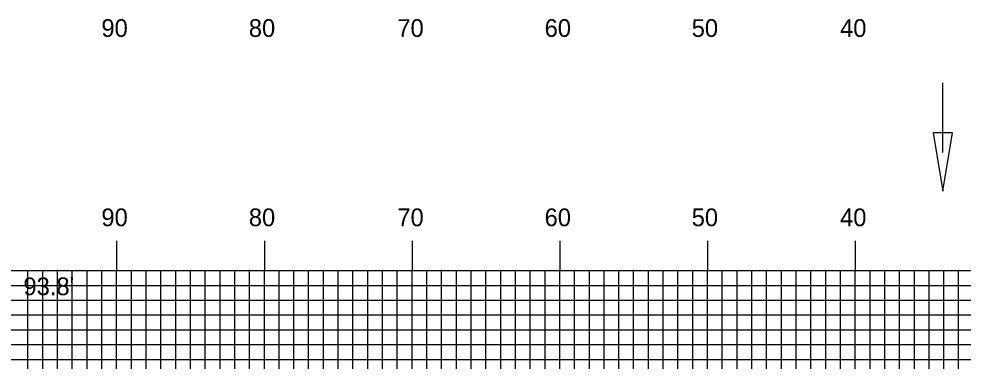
# Model space of a CAD drawing. Extents: x 1770448 to 1770792, y 442591 to 442811.
# Drawn here: x 1770517.4 to 1770581.3, y 442717.5 to 442740.7 of the extents above; entities that cross this region are included whole.
import ezdxf

# ---------------------------------------------------------------- set-up
doc = ezdxf.new("R2010")
doc.units = 0
for name, color, linetype in [('D_Drainage_Ditch_Line', 7, 'Continuous'), ('D_Text_Standard', 7, 'Continuous'), ('H_V ANNOTATION', 7, 'Continuous'), ('MAJOR', 7, 'Continuous'), ('MINOR', 7, 'Continuous')]:
    doc.layers.add(name, color=color, linetype=linetype)

msp = doc.modelspace()

# ---------------------------------------------------------------- linework, layer by layer
at = {"layer": 'D_Drainage_Ditch_Line'}
msp.add_line((1770579.979, 442731.659), (1770579.979, 442736.358), dxfattribs=at)
msp.add_lwpolyline([(1770580.635, 442732.972), (1770579.323, 442732.972), (1770579.979, 442729.035)], close=True, dxfattribs=at)
at = {"layer": 'MAJOR'}
for p, q in [((1770524.041, 442725.669), (1770524.041, 442723.665)), ((1770534.041, 442725.669), (1770534.041, 442723.665)), ((1770544.041, 442725.669), (1770544.041, 442723.665)), ((1770554.041, 442725.669), (1770554.041, 442723.665)), ((1770564.041, 442725.669), (1770564.041, 442723.665)), ((1770574.041, 442725.669), (1770574.041, 442723.665)), ((1770474.041, 442723.665), (1770754.041, 442723.665)), ((1770474.041, 442723.665), (1770754.041, 442723.665)), ((1770524.041, 442678.665), (1770524.041, 442723.665)), ((1770534.041, 442678.665), (1770534.041, 442723.665)), ((1770544.041, 442678.665), (1770544.041, 442723.665)), ((1770554.041, 442678.665), (1770554.041, 442723.665)), ((1770564.041, 442678.665), (1770564.041, 442723.665)), ((1770574.041, 442678.665), (1770574.041, 442723.665)), ((1770474.041, 442718.665), (1770754.041, 442718.665))]:
    msp.add_line(p, q, dxfattribs=at)
at = {"layer": 'MINOR'}
for p, q in [((1770518.041, 442678.665), (1770518.041, 442723.665)), ((1770519.041, 442678.665), (1770519.041, 442723.665)), ((1770520.041, 442678.665), (1770520.041, 442723.665)), ((1770521.041, 442678.665), (1770521.041, 442723.665)), ((1770522.041, 442678.665), (1770522.041, 442723.665)), ((1770523.041, 442678.665), (1770523.041, 442723.665)), ((1770525.041, 442678.665), (1770525.041, 442723.665)), ((1770526.041, 442678.665), (1770526.041, 442723.665)), ((1770527.041, 442678.665), (1770527.041, 442723.665)), ((1770528.041, 442678.665), (1770528.041, 442723.665)), ((1770529.041, 442678.665), (1770529.041, 442723.665)), ((1770530.041, 442678.665), (1770530.041, 442723.665)), ((1770531.041, 442678.665), (1770531.041, 442723.665)), ((1770532.041, 442678.665), (1770532.041, 442723.665)), ((1770533.041, 442678.665), (1770533.041, 442723.665)), ((1770535.041, 442678.665), (1770535.041, 442723.665)), ((1770536.041, 442678.665), (1770536.041, 442723.665)), ((1770537.041, 442678.665), (1770537.041, 442723.665)), ((1770538.041, 442678.665), (1770538.041, 442723.665)), ((1770539.041, 442678.665), (1770539.041, 442723.665)), ((1770540.041, 442678.665), (1770540.041, 442723.665)), ((1770541.041, 442678.665), (1770541.041, 442723.665)), ((1770542.041, 442678.665), (1770542.041, 442723.665)), ((1770543.041, 442678.665), (1770543.041, 442723.665)), ((1770545.041, 442678.665), (1770545.041, 442723.665)), ((1770546.041, 442678.665), (1770546.041, 442723.665)), ((1770547.041, 442678.665), (1770547.041, 442723.665)), ((1770548.041, 442678.665), (1770548.041, 442723.665)), ((1770549.041, 442678.665), (1770549.041, 442723.665)), ((1770550.041, 442678.665), (1770550.041, 442723.665)), ((1770551.041, 442678.665), (1770551.041, 442723.665)), ((1770552.041, 442678.665), (1770552.041, 442723.665)), ((1770553.041, 442678.665), (1770553.041, 442723.665)), ((1770555.041, 442678.665), (1770555.041, 442723.665)), ((1770556.041, 442678.665), (1770556.041, 442723.665)), ((1770557.041, 442678.665), (1770557.041, 442723.665)), ((1770558.041, 442678.665), (1770558.041, 442723.665)), ((1770559.041, 442678.665), (1770559.041, 442723.665)), ((1770560.041, 442678.665), (1770560.041, 442723.665)), ((1770561.041, 442678.665), (1770561.041, 442723.665)), ((1770562.041, 442678.665), (1770562.041, 442723.665)), ((1770563.041, 442678.665), (1770563.041, 442723.665)), ((1770565.041, 442678.665), (1770565.041, 442723.665)), ((1770566.041, 442678.665), (1770566.041, 442723.665)), ((1770567.041, 442678.665), (1770567.041, 442723.665)), ((1770568.041, 442678.665), (1770568.041, 442723.665)), ((1770569.041, 442678.665), (1770569.041, 442723.665)), ((1770570.041, 442678.665), (1770570.041, 442723.665)), ((1770571.041, 442678.665), (1770571.041, 442723.665)), ((1770572.041, 442678.665), (1770572.041, 442723.665)), ((1770573.041, 442678.665), (1770573.041, 442723.665)), ((1770575.041, 442678.665), (1770575.041, 442723.665)), ((1770576.041, 442678.665), (1770576.041, 442723.665)), ((1770577.041, 442678.665), (1770577.041, 442723.665)), ((1770578.041, 442678.665), (1770578.041, 442723.665)), ((1770579.041, 442678.665), (1770579.041, 442723.665)), ((1770580.041, 442678.665), (1770580.041, 442723.665)), ((1770581.041, 442678.665), (1770581.041, 442723.665)), ((1770474.041, 442722.665), (1770754.041, 442722.665)), ((1770474.041, 442721.665), (1770754.041, 442721.665)), ((1770474.041, 442720.665), (1770754.041, 442720.665)), ((1770474.041, 442719.665), (1770754.041, 442719.665)), ((1770474.041, 442717.665), (1770754.041, 442717.665))]:
    msp.add_line(p, q, dxfattribs=at)

# ---------------------------------------------------------------- texts
at = {"layer": 'D_Text_Standard'}
msp.add_text("93.8'", height=1.2, dxfattribs=at).set_placement((1770517.736, 442722.002))
at = {"layer": 'H_V ANNOTATION'}
for s, p in [('90', (1770523.013, 442739.465)), ('80', (1770532.992, 442739.465)), ('70', (1770543.045, 442739.465)), ('60', (1770553.013, 442739.465)), ('50', (1770562.97, 442739.465)), ('40', (1770573.013, 442739.465)), ('90', (1770523.013, 442726.665)), ('80', (1770532.992, 442726.665)), ('70', (1770543.045, 442726.665)), ('60', (1770553.013, 442726.665)), ('50', (1770562.97, 442726.665)), ('40', (1770573.013, 442726.665))]:
    msp.add_text(s, height=1.2, dxfattribs=at).set_placement(p)

doc.saveas('drawing.dxf')
